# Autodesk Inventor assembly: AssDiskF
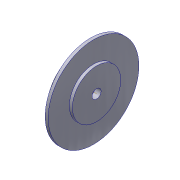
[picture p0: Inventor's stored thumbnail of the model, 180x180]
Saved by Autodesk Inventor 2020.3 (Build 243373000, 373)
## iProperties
Created: 2013-08
Part Number: AssDiskF
Document SubType Name: Assembly
Designer: hunter love
Mass: 142.998 g
Surface Area: 599.909 cm^2
Volume: 142.998 cm^3
Density: 1 g/cm^3
Author: hunter love
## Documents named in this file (3)
- C:\Users\admin\Desktop\disegno\disegno inventor thang\ScrollCompressorInv\AssDiskF.iam
- C:\Users\admin\Desktop\disegno\disegno inventor thang\ScrollCompressorInv\WheelFBase.ipt
- C:\Users\admin\Desktop\disegno\disegno inventor thang\ScrollCompressorInv\WheelFGear.ipt
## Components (2 placed, 2 different names)
1. WheelFBase:1 — Mate:1, Mate:2, Mate:3, Coincidente:4
2. WheelFGear:1 — Mate:1, Mate:2, Mate:3
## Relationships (4: Mate 4)
- Mate:1: WheelFBase:1 ↔ WheelFGear:1
- Mate:2: WheelFBase:1 ↔ WheelFGear:1
- Mate:3: WheelFBase:1 ↔ WheelFGear:1
- Coincidente:4 [Mate]: WheelFBase:1
